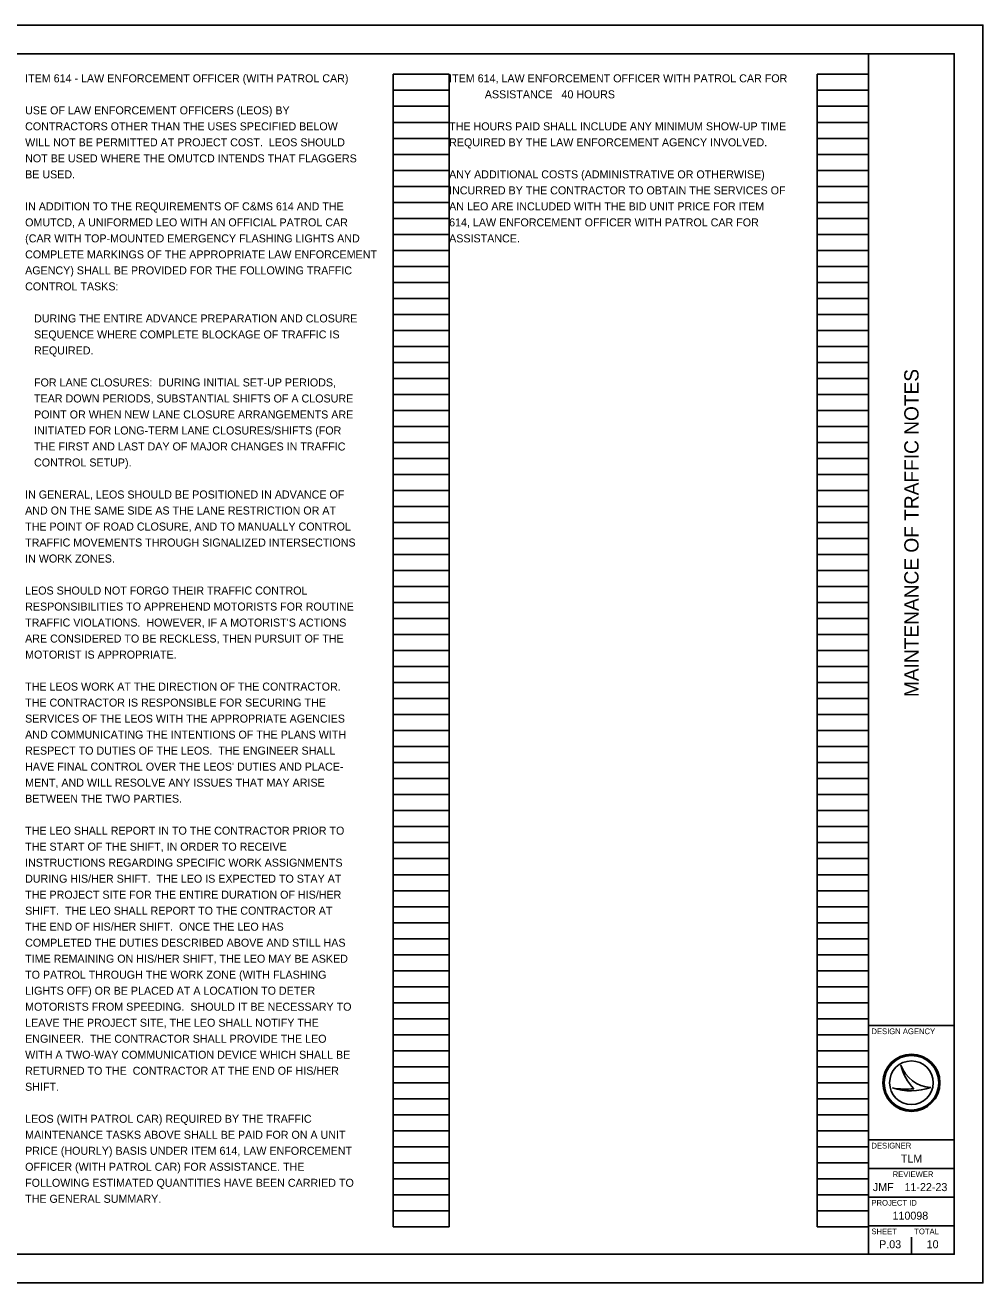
# Model space of a CAD drawing. Extents: x 0 to 34, y 0 to 22.
# Drawn here: x 17.24 to 34, y 0 to 22 of the extents above; entities that cross this region are included whole.
import ezdxf

# ---------------------------------------------------------------- set-up
doc = ezdxf.new("R2010")
doc.units = 0
for name, color, linetype in [('SH_Border', 7, 'Continuous'), ('SH_Cut_Line', 7, 'Continuous'), ('SH_Data', 7, 'Continuous'), ('SH_Text', 7, 'Continuous')]:
    doc.layers.add(name, color=color, linetype=linetype)

msp = doc.modelspace()

# ---------------------------------------------------------------- linework, layer by layer
at = {"layer": 'SH_Border'}
for p, q in [((32, 0.5), (32, 21.5)), ((32, 4.5), (33.5, 4.5)), ((32, 2.5), (33.5, 2.5)), ((32, 2), (33.5, 2)), ((32, 1.5), (33.5, 1.5)), ((32, 1), (33.5, 1))]:
    msp.add_line(p, q, dxfattribs=at)
msp.add_lwpolyline([(1.5, 21.5), (33.5, 21.5), (33.5, 0.5), (1.5, 0.5)], close=True, dxfattribs=at)
at = {"layer": 'SH_Cut_Line'}
msp.add_lwpolyline([(0, 0), (34, 0), (34, 22), (0, 22)], close=True, dxfattribs=at)
at = {"layer": 'SH_Data'}
for p, q in [((23.68, 0.98), (23.68, 21.14)), ((23.68, 21.14), (24.66, 21.14)), ((24.66, 0.98), (24.66, 21.14)), ((31.1, 0.98), (31.1, 21.14)), ((31.1, 21.14), (32, 21.14)), ((32, 0.98), (32, 21.14)), ((23.68, 20.86), (24.66, 20.86)), ((31.1, 20.86), (32, 20.86)), ((23.68, 20.58), (24.66, 20.58)), ((31.1, 20.58), (32, 20.58)), ((23.68, 20.3), (24.66, 20.3)), ((31.1, 20.3), (32, 20.3)), ((23.68, 20.02), (24.66, 20.02)), ((31.1, 20.02), (32, 20.02)), ((23.68, 19.74), (24.66, 19.74)), ((31.1, 19.74), (32, 19.74)), ((23.68, 19.46), (24.66, 19.46)), ((31.1, 19.46), (32, 19.46)), ((23.68, 19.18), (24.66, 19.18)), ((31.1, 19.18), (32, 19.18)), ((23.68, 18.9), (24.66, 18.9)), ((31.1, 18.9), (32, 18.9)), ((23.68, 18.62), (24.66, 18.62)), ((31.1, 18.62), (32, 18.62)), ((23.68, 18.34), (24.66, 18.34)), ((31.1, 18.34), (32, 18.34)), ((23.68, 18.06), (24.66, 18.06)), ((31.1, 18.06), (32, 18.06)), ((23.68, 17.78), (24.66, 17.78)), ((31.1, 17.78), (32, 17.78)), ((23.68, 17.5), (24.66, 17.5)), ((31.1, 17.5), (32, 17.5)), ((23.68, 17.22), (24.66, 17.22)), ((31.1, 17.22), (32, 17.22)), ((23.68, 16.94), (24.66, 16.94)), ((31.1, 16.94), (32, 16.94)), ((23.68, 16.66), (24.66, 16.66)), ((31.1, 16.66), (32, 16.66)), ((23.68, 16.38), (24.66, 16.38)), ((31.1, 16.38), (32, 16.38)), ((23.68, 16.1), (24.66, 16.1)), ((31.1, 16.1), (32, 16.1)), ((23.68, 15.82), (24.66, 15.82)), ((31.1, 15.82), (32, 15.82)), ((23.68, 15.54), (24.66, 15.54)), ((31.1, 15.54), (32, 15.54)), ((23.68, 15.26), (24.66, 15.26)), ((31.1, 15.26), (32, 15.26)), ((23.68, 14.98), (24.66, 14.98)), ((31.1, 14.98), (32, 14.98)), ((23.68, 14.7), (24.66, 14.7)), ((31.1, 14.7), (32, 14.7)), ((23.68, 14.42), (24.66, 14.42)), ((31.1, 14.42), (32, 14.42)), ((23.68, 14.14), (24.66, 14.14)), ((31.1, 14.14), (32, 14.14)), ((23.68, 13.86), (24.66, 13.86)), ((31.1, 13.86), (32, 13.86)), ((23.68, 13.58), (24.66, 13.58)), ((31.1, 13.58), (32, 13.58)), ((23.68, 13.3), (24.66, 13.3)), ((31.1, 13.3), (32, 13.3)), ((23.68, 13.02), (24.66, 13.02)), ((31.1, 13.02), (32, 13.02)), ((23.68, 12.74), (24.66, 12.74)), ((31.1, 12.74), (32, 12.74)), ((23.68, 12.46), (24.66, 12.46)), ((31.1, 12.46), (32, 12.46)), ((23.68, 12.18), (24.66, 12.18)), ((31.1, 12.18), (32, 12.18)), ((23.68, 11.9), (24.66, 11.9)), ((31.1, 11.9), (32, 11.9)), ((23.68, 11.62), (24.66, 11.62)), ((31.1, 11.62), (32, 11.62)), ((23.68, 11.34), (24.66, 11.34)), ((31.1, 11.34), (32, 11.34)), ((23.68, 11.06), (24.66, 11.06)), ((31.1, 11.06), (32, 11.06)), ((23.68, 10.78), (24.66, 10.78)), ((31.1, 10.78), (32, 10.78)), ((23.68, 10.5), (24.66, 10.5)), ((31.1, 10.5), (32, 10.5)), ((23.68, 10.22), (24.66, 10.22)), ((31.1, 10.22), (32, 10.22)), ((23.68, 9.94), (24.66, 9.94)), ((31.1, 9.94), (32, 9.94)), ((23.68, 9.66), (24.66, 9.66)), ((31.1, 9.66), (32, 9.66)), ((23.68, 9.38), (24.66, 9.38)), ((31.1, 9.38), (32, 9.38)), ((23.68, 9.1), (24.66, 9.1)), ((31.1, 9.1), (32, 9.1)), ((23.68, 8.82), (24.66, 8.82)), ((31.1, 8.82), (32, 8.82)), ((23.68, 8.54), (24.66, 8.54)), ((31.1, 8.54), (32, 8.54)), ((23.68, 8.26), (24.66, 8.26)), ((31.1, 8.26), (32, 8.26)), ((23.68, 7.98), (24.66, 7.98)), ((31.1, 7.98), (32, 7.98)), ((23.68, 7.7), (24.66, 7.7)), ((31.1, 7.7), (32, 7.7)), ((23.68, 7.42), (24.66, 7.42)), ((31.1, 7.42), (32, 7.42)), ((23.68, 7.14), (24.66, 7.14)), ((31.1, 7.14), (32, 7.14)), ((23.68, 6.86), (24.66, 6.86)), ((31.1, 6.86), (32, 6.86)), ((23.68, 6.58), (24.66, 6.58)), ((31.1, 6.58), (32, 6.58)), ((23.68, 6.3), (24.66, 6.3)), ((31.1, 6.3), (32, 6.3)), ((23.68, 6.02), (24.66, 6.02)), ((31.1, 6.02), (32, 6.02)), ((23.68, 5.74), (24.66, 5.74)), ((31.1, 5.74), (32, 5.74)), ((23.68, 5.46), (24.66, 5.46)), ((31.1, 5.46), (32, 5.46)), ((23.68, 5.18), (24.66, 5.18)), ((31.1, 5.18), (32, 5.18)), ((23.68, 4.9), (24.66, 4.9)), ((31.1, 4.9), (32, 4.9)), ((23.68, 4.62), (24.66, 4.62)), ((31.1, 4.62), (32, 4.62)), ((23.68, 4.34), (24.66, 4.34)), ((31.1, 4.34), (32, 4.34)), ((23.68, 4.06), (24.66, 4.06)), ((31.1, 4.06), (32, 4.06)), ((23.68, 3.78), (24.66, 3.78)), ((31.1, 3.78), (32, 3.78)), ((32.567, 3.81), (32.567, 3.81)), ((23.68, 3.5), (24.66, 3.5)), ((31.1, 3.5), (32, 3.5)), ((32.417, 3.41), (32.417, 3.41)), ((32.75, 3.5), (32.75, 3.5)), ((33.087, 3.419), (33.087, 3.419)), ((23.68, 3.22), (24.66, 3.22)), ((31.1, 3.22), (32, 3.22)), ((23.68, 2.94), (24.66, 2.94)), ((31.1, 2.94), (32, 2.94)), ((23.68, 2.66), (24.66, 2.66)), ((31.1, 2.66), (32, 2.66)), ((23.68, 2.38), (24.66, 2.38)), ((31.1, 2.38), (32, 2.38)), ((23.68, 2.1), (24.66, 2.1)), ((31.1, 2.1), (32, 2.1)), ((23.68, 1.82), (24.66, 1.82)), ((31.1, 1.82), (32, 1.82)), ((23.68, 1.54), (24.66, 1.54)), ((31.1, 1.54), (32, 1.54)), ((23.68, 1.26), (24.66, 1.26)), ((31.1, 1.26), (32, 1.26)), ((23.68, 0.98), (24.66, 0.98)), ((31.1, 0.98), (32, 0.98)), ((32.375, 0.675), (32.375, 0.675)), ((32.75, 0.5), (32.75, 0.8))]:
    msp.add_line(p, q, dxfattribs=at)
for radius in [0.5, 0.477, 0.477, 0.382]:
    msp.add_circle((32.75, 3.5), radius, dxfattribs=at)
for centre, radius, start, end in [((33.116, 3.998), 0.58, 198.9257, 198.9319), ((33.347, 3.97), 0.796, 191.6379, 191.6421), ((33.116, 3.998), 0.58, 198.9319, 267.1657), ((33.347, 3.97), 0.796, 191.6421, 226.0947), ((32.739, 4.37), 1.013, 251.4576, 290.0832), ((32.648, 4.654), 1.266, 259.4964, 259.4995), ((32.739, 4.37), 1.013, 251.4527, 251.4576), ((32.648, 4.654), 1.266, 259.4995, 276.6672)]:
    msp.add_arc(centre, radius, start, end, dxfattribs=at)

# ---------------------------------------------------------------- texts
msp.add_text('MAINTENANCE OF TRAFFIC NOTES', height=0.25, rotation=90, dxfattribs=at).set_placement((32.875, 10.247))
for s, height, p in [('DESIGN AGENCY', 0.1, (32.05, 4.35)), ('DESIGNER', 0.1, (32.05, 2.35)), ('TLM', 0.14, (32.565, 2.105)), ('REVIEWER', 0.1, (32.422, 1.85)), ('JMF', 0.14, (32.075, 1.605)), ('11-22-23', 0.14, (32.629, 1.605)), ('PROJECT ID', 0.1, (32.05, 1.35)), ('110098', 0.14, (32.419, 1.105)), ('SHEET', 0.1, (32.05, 0.85)), ('TOTAL', 0.1, (32.8, 0.85)), ('P.03', 0.14, (32.185, 0.605)), ('10', 0.14, (33.017, 0.605))]:
    msp.add_text(s, height=height, dxfattribs=at).set_placement(p)
at = {"layer": 'SH_Text'}
for s, p in [('ITEM 614 - LAW ENFORCEMENT OFFICER (WITH PATROL CAR)', (17.24, 21)), ('ITEM 614, LAW ENFORCEMENT OFFICER WITH PATROL CAR FOR', (24.66, 21)), ('            ASSISTANCE   40 HOURS', (24.66, 20.72)), ('USE OF LAW ENFORCEMENT OFFICERS (LEOS) BY', (17.24, 20.44)), ('CONTRACTORS OTHER THAN THE USES SPECIFIED BELOW', (17.24, 20.16)), ('THE HOURS PAID SHALL INCLUDE ANY MINIMUM SHOW-UP TIME', (24.66, 20.16)), ('WILL NOT BE PERMITTED AT PROJECT COST.  LEOS SHOULD', (17.24, 19.88)), ('REQUIRED BY THE LAW ENFORCEMENT AGENCY INVOLVED.', (24.66, 19.88)), ('NOT BE USED WHERE THE OMUTCD INTENDS THAT FLAGGERS', (17.24, 19.6)), ('BE USED.', (17.24, 19.32)), ('ANY ADDITIONAL COSTS (ADMINISTRATIVE OR OTHERWISE)', (24.66, 19.32)), ('INCURRED BY THE CONTRACTOR TO OBTAIN THE SERVICES OF', (24.66, 19.04)), ('IN ADDITION TO THE REQUIREMENTS OF C&MS 614 AND THE', (17.24, 18.76)), ('AN LEO ARE INCLUDED WITH THE BID UNIT PRICE FOR ITEM', (24.66, 18.76)), ('OMUTCD, A UNIFORMED LEO WITH AN OFFICIAL PATROL CAR', (17.24, 18.48)), ('614, LAW ENFORCEMENT OFFICER WITH PATROL CAR FOR', (24.66, 18.48)), ('(CAR WITH TOP-MOUNTED EMERGENCY FLASHING LIGHTS AND', (17.24, 18.2)), ('ASSISTANCE.', (24.66, 18.2)), ('COMPLETE MARKINGS OF THE APPROPRIATE LAW ENFORCEMENT', (17.24, 17.92)), ('AGENCY) SHALL BE PROVIDED FOR THE FOLLOWING TRAFFIC', (17.24, 17.64)), ('CONTROL TASKS:', (17.24, 17.36)), ('   DURING THE ENTIRE ADVANCE PREPARATION AND CLOSURE', (17.24, 16.8)), ('   SEQUENCE WHERE COMPLETE BLOCKAGE OF TRAFFIC IS', (17.24, 16.52)), ('   REQUIRED.', (17.24, 16.24)), ('   FOR LANE CLOSURES:  DURING INITIAL SET-UP PERIODS,', (17.24, 15.68)), ('   TEAR DOWN PERIODS, SUBSTANTIAL SHIFTS OF A CLOSURE', (17.24, 15.4)), ('   POINT OR WHEN NEW LANE CLOSURE ARRANGEMENTS ARE', (17.24, 15.12)), ('   INITIATED FOR LONG-TERM LANE CLOSURES/SHIFTS (FOR', (17.24, 14.84)), ('   THE FIRST AND LAST DAY OF MAJOR CHANGES IN TRAFFIC', (17.24, 14.56)), ('   CONTROL SETUP).', (17.24, 14.28)), ('IN GENERAL, LEOS SHOULD BE POSITIONED IN ADVANCE OF', (17.24, 13.72)), ('AND ON THE SAME SIDE AS THE LANE RESTRICTION OR AT', (17.24, 13.44)), ('THE POINT OF ROAD CLOSURE, AND TO MANUALLY CONTROL', (17.24, 13.16)), ('TRAFFIC MOVEMENTS THROUGH SIGNALIZED INTERSECTIONS', (17.24, 12.88)), ('IN WORK ZONES.', (17.24, 12.6)), ('LEOS SHOULD NOT FORGO THEIR TRAFFIC CONTROL', (17.24, 12.04)), ('RESPONSIBILITIES TO APPREHEND MOTORISTS FOR ROUTINE', (17.24, 11.76)), ("TRAFFIC VIOLATIONS.  HOWEVER, IF A MOTORIST'S ACTIONS", (17.24, 11.48)), ('ARE CONSIDERED TO BE RECKLESS, THEN PURSUIT OF THE', (17.24, 11.2)), ('MOTORIST IS APPROPRIATE.', (17.24, 10.92)), ('THE LEOS WORK AT THE DIRECTION OF THE CONTRACTOR.', (17.24, 10.36)), ('THE CONTRACTOR IS RESPONSIBLE FOR SECURING THE', (17.24, 10.08)), ('SERVICES OF THE LEOS WITH THE APPROPRIATE AGENCIES', (17.24, 9.8)), ('AND COMMUNICATING THE INTENTIONS OF THE PLANS WITH', (17.24, 9.52)), ('RESPECT TO DUTIES OF THE LEOS.  THE ENGINEER SHALL', (17.24, 9.24)), ("HAVE FINAL CONTROL OVER THE LEOS' DUTIES AND PLACE-", (17.24, 8.96)), ('MENT, AND WILL RESOLVE ANY ISSUES THAT MAY ARISE', (17.24, 8.68)), ('BETWEEN THE TWO PARTIES.', (17.24, 8.4)), ('THE LEO SHALL REPORT IN TO THE CONTRACTOR PRIOR TO', (17.24, 7.84)), ('THE START OF THE SHIFT, IN ORDER TO RECEIVE', (17.24, 7.56)), ('INSTRUCTIONS REGARDING SPECIFIC WORK ASSIGNMENTS', (17.24, 7.28)), ('DURING HIS/HER SHIFT.  THE LEO IS EXPECTED TO STAY AT', (17.24, 7)), ('THE PROJECT SITE FOR THE ENTIRE DURATION OF HIS/HER', (17.24, 6.72)), ('SHIFT.  THE LEO SHALL REPORT TO THE CONTRACTOR AT', (17.24, 6.44)), ('THE END OF HIS/HER SHIFT.  ONCE THE LEO HAS', (17.24, 6.16)), ('COMPLETED THE DUTIES DESCRIBED ABOVE AND STILL HAS', (17.24, 5.88)), ('TIME REMAINING ON HIS/HER SHIFT, THE LEO MAY BE ASKED', (17.24, 5.6)), ('TO PATROL THROUGH THE WORK ZONE (WITH FLASHING', (17.24, 5.32)), ('LIGHTS OFF) OR BE PLACED AT A LOCATION TO DETER', (17.24, 5.04)), ('MOTORISTS FROM SPEEDING.  SHOULD IT BE NECESSARY TO', (17.24, 4.76)), ('LEAVE THE PROJECT SITE, THE LEO SHALL NOTIFY THE', (17.24, 4.48)), ('ENGINEER.  THE CONTRACTOR SHALL PROVIDE THE LEO', (17.24, 4.2)), ('WITH A TWO-WAY COMMUNICATION DEVICE WHICH SHALL BE', (17.24, 3.92)), ('RETURNED TO THE  CONTRACTOR AT THE END OF HIS/HER', (17.24, 3.64)), ('SHIFT.  ', (17.24, 3.36)), ('LEOS (WITH PATROL CAR) REQUIRED BY THE TRAFFIC', (17.24, 2.8)), ('MAINTENANCE TASKS ABOVE SHALL BE PAID FOR ON A UNIT', (17.24, 2.52)), ('PRICE (HOURLY) BASIS UNDER ITEM 614, LAW ENFORCEMENT', (17.24, 2.24)), ('OFFICER (WITH PATROL CAR) FOR ASSISTANCE. THE', (17.24, 1.96)), ('FOLLOWING ESTIMATED QUANTITIES HAVE BEEN CARRIED TO', (17.24, 1.68)), ('THE GENERAL SUMMARY.', (17.24, 1.4))]:
    msp.add_text(s, height=0.14, dxfattribs=at).set_placement(p)

doc.saveas('drawing.dxf')
